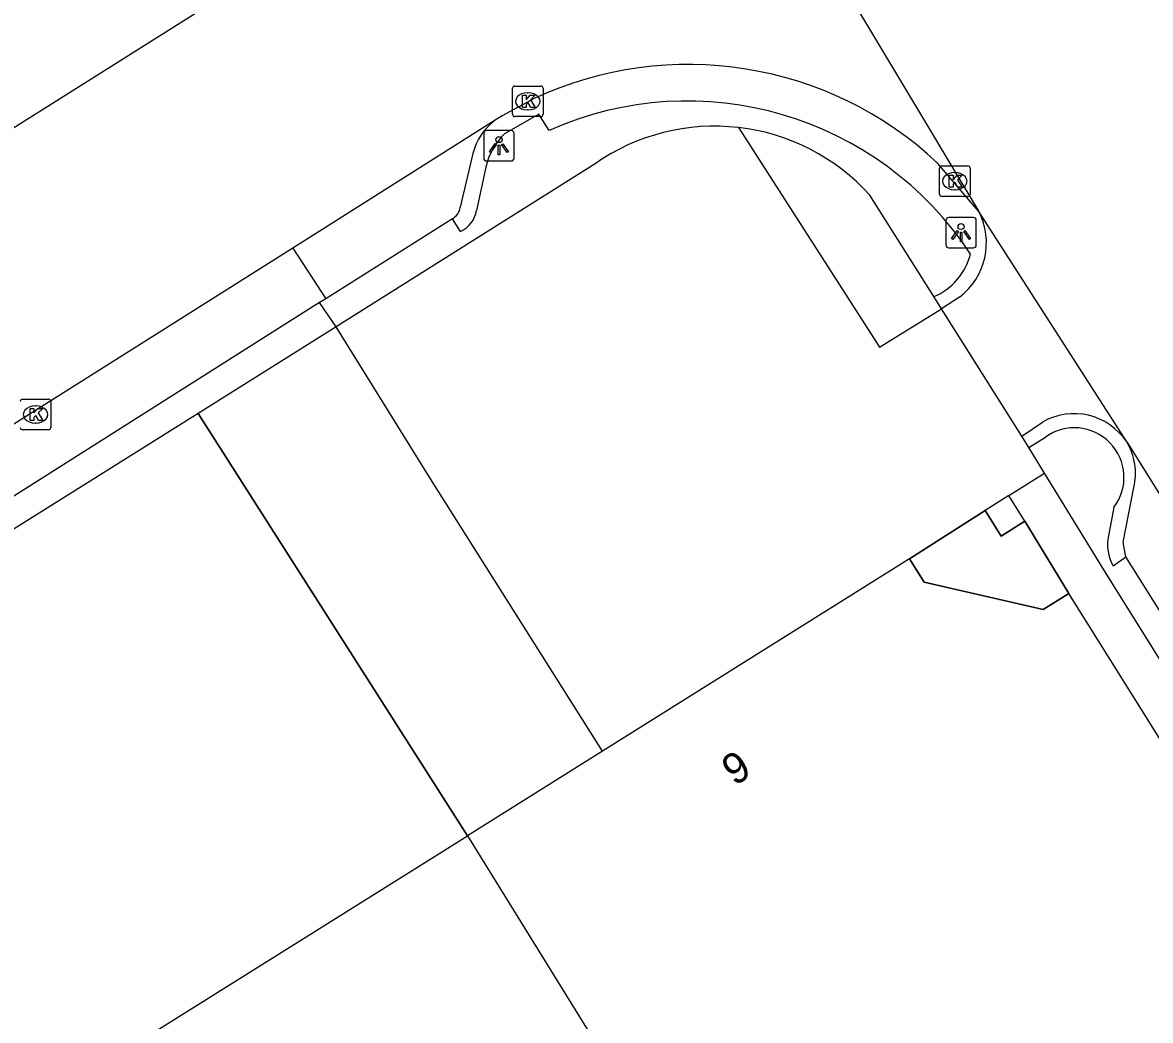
# Model space of a CAD drawing. Extents: x 158461 to 159795, y 387220 to 388672.
# Drawn here: x 158632.42 to 158669.4, y 387794.72 to 387827.43 of the extents above; entities that cross this region are included whole.
import ezdxf

# ---------------------------------------------------------------- set-up
doc = ezdxf.new("R2010")
doc.units = 0
for name, color, linetype in [('IMGEO_Hek', 7, 'Continuous'), ('IMGEO_Kolk', 7, 'Continuous'), ('IMGEO_Lichtpunt', 7, 'Continuous'), ('IMGEO_Pand', 7, 'Continuous'), ('IMGEO_Pand_nummerreeks', 7, 'Continuous'), ('IMGEO_Pand_overbouw', 7, 'Continuous'), ('IMGEO_Parkeervlak_open', 7, 'Continuous'), ('IMGEO_Rijbaan_lokaal_gesloten', 7, 'Continuous'), ('IMGEO_Rijbaan_lokaal_open', 7, 'Continuous'), ('IMGEO_Voetpad_open', 7, 'Continuous')]:
    doc.layers.add(name, color=color, linetype=linetype)

msp = doc.modelspace()

# ---------------------------------------------------------------- linework, layer by layer
at = {"layer": 'IMGEO_Hek'}
msp.add_lwpolyline([(158647.008, 387800.772), (158638.179, 387814.618)], dxfattribs=at)
at = {"layer": 'IMGEO_Kolk'}
for p, q in [((158648.49, 387824.421), (158648.49, 387825.273)), ((158648.565, 387825.347), (158649.417, 387825.347)), ((158648.978, 387825.127), (158649.003, 387825.127)), ((158649.491, 387825.273), (158649.491, 387824.421)), ((158649.417, 387824.347), (158648.565, 387824.347)), ((158649.001, 387824.567), (158648.976, 387824.567)), ((158662.489, 387821.803), (158662.489, 387822.655)), ((158662.564, 387822.729), (158663.416, 387822.729)), ((158662.977, 387822.509), (158663.002, 387822.509)), ((158663.49, 387822.655), (158663.49, 387821.803)), ((158663.416, 387821.729), (158662.564, 387821.729)), ((158663, 387821.949), (158662.975, 387821.949)), ((158632.424, 387815.082), (158633.276, 387815.082)), ((158632.837, 387814.862), (158632.862, 387814.862)), ((158633.35, 387815.008), (158633.35, 387814.156)), ((158633.276, 387814.082), (158632.424, 387814.082)), ((158632.86, 387814.302), (158632.835, 387814.302))]:
    msp.add_line(p, q, dxfattribs=at)
for points in [[(158648.49, 387824.421), (158648.49, 387825.273)], [(158648.565, 387825.347), (158649.417, 387825.347)], [(158648.811, 387825.047), (158648.934, 387825.047), (158648.934, 387824.896), (158649.064, 387825.047), (158649.228, 387825.047), (158649.082, 387824.896), (158649.235, 387824.647), (158649.083, 387824.647), (158648.998, 387824.811), (158648.934, 387824.744), (158648.934, 387824.647), (158648.811, 387824.647), (158648.811, 387825.047)], [(158649.491, 387825.273), (158649.491, 387824.421)], [(158649.417, 387824.347), (158648.565, 387824.347)], [(158662.489, 387821.803), (158662.489, 387822.655)], [(158662.564, 387822.729), (158663.416, 387822.729)], [(158663.49, 387822.655), (158663.49, 387821.803)], [(158662.81, 387822.429), (158662.933, 387822.429), (158662.933, 387822.278), (158663.063, 387822.429), (158663.227, 387822.429), (158663.081, 387822.278), (158663.234, 387822.029), (158663.082, 387822.029), (158662.997, 387822.193), (158662.933, 387822.126), (158662.933, 387822.029), (158662.81, 387822.029), (158662.81, 387822.429)], [(158663.416, 387821.729), (158662.564, 387821.729)], [(158632.424, 387815.082), (158633.276, 387815.082)], [(158632.67, 387814.782), (158632.793, 387814.782), (158632.793, 387814.631), (158632.923, 387814.782), (158633.087, 387814.782), (158632.941, 387814.631), (158633.094, 387814.382), (158632.942, 387814.382), (158632.857, 387814.546), (158632.793, 387814.479), (158632.793, 387814.382), (158632.67, 387814.382), (158632.67, 387814.782)], [(158633.35, 387815.008), (158633.35, 387814.156)], [(158633.276, 387814.082), (158632.424, 387814.082)]]:
    msp.add_lwpolyline(points, dxfattribs=at)
for centre, start, end in [((158648.567, 387825.271), 91.552, 178.448), ((158648.567, 387825.271), 91.552, 178.448), ((158649.415, 387825.271), 1.552, 88.448), ((158649.415, 387825.271), 1.552, 88.448), ((158648.567, 387824.423), 181.552, 268.448), ((158648.567, 387824.423), 181.552, 268.448), ((158649.415, 387824.423), 271.552, 358.448), ((158649.415, 387824.423), 271.552, 358.448), ((158662.566, 387822.653), 91.552, 178.448), ((158662.566, 387822.653), 91.552, 178.448), ((158663.414, 387822.653), 1.552, 88.448), ((158663.414, 387822.653), 1.552, 88.448), ((158662.566, 387821.805), 181.552, 268.448), ((158662.566, 387821.805), 181.552, 268.448), ((158663.414, 387821.805), 271.552, 358.448), ((158663.414, 387821.805), 271.552, 358.448), ((158632.426, 387815.006), 91.552, 178.448), ((158632.426, 387815.006), 91.552, 178.448), ((158633.274, 387815.006), 1.552, 88.448), ((158633.274, 387815.006), 1.552, 88.448), ((158632.426, 387814.158), 181.552, 268.448), ((158632.426, 387814.158), 181.552, 268.448), ((158633.274, 387814.158), 271.552, 358.448), ((158633.274, 387814.158), 271.552, 358.448)]:
    msp.add_arc(centre, 0.0765, start, end, dxfattribs=at)
for centre, major_axis, ratio, start_param, end_param in [((158648.977, 387824.847), (-0.387, 0.002), 0.722429, 4.712389, 7.853982), ((158649.002, 387824.847), (-0.39, 0.002), 0.717154, 1.570796, 4.712389), ((158662.976, 387822.229), (-0.387, 0.002), 0.722429, 4.712389, 7.853982), ((158663.001, 387822.229), (-0.39, 0.002), 0.717154, 1.570796, 4.712389), ((158632.836, 387814.582), (-0.387, 0.002), 0.722429, 4.712389, 7.853982), ((158632.861, 387814.582), (-0.39, 0.002), 0.717154, 1.570796, 4.712389)]:
    msp.add_ellipse(centre, major_axis=major_axis, ratio=ratio, start_param=start_param, end_param=end_param, dxfattribs=at)
at = {"layer": 'IMGEO_Lichtpunt'}
for p, q in [((158647.546, 387823.795), (158647.546, 387822.988)), ((158647.546, 387823.795), (158647.546, 387822.988)), ((158648.448, 387823.89), (158647.64, 387823.89)), ((158648.448, 387823.89), (158647.64, 387823.89)), ((158648.542, 387822.988), (158648.542, 387823.795)), ((158648.542, 387822.988), (158648.542, 387823.795)), ((158647.64, 387822.894), (158648.448, 387822.894)), ((158647.64, 387822.894), (158648.448, 387822.894)), ((158663.599, 387821.04), (158662.791, 387821.04)), ((158663.599, 387821.04), (158662.791, 387821.04)), ((158662.697, 387820.945), (158662.697, 387820.138)), ((158662.697, 387820.945), (158662.697, 387820.138)), ((158663.693, 387820.138), (158663.693, 387820.945)), ((158663.693, 387820.138), (158663.693, 387820.945)), ((158662.791, 387820.044), (158663.599, 387820.044)), ((158662.791, 387820.044), (158663.599, 387820.044))]:
    msp.add_line(p, q, dxfattribs=at)
for points in [[(158647.92, 387823.459), (158647.959, 387823.431), (158647.771, 387823.169), (158647.733, 387823.196), (158647.92, 387823.459)], [(158648.022, 387823.411), (158648.069, 387823.411), (158648.069, 387823.089), (158648.022, 387823.089), (158648.022, 387823.411)], [(158648.132, 387823.431), (158648.17, 387823.458), (158648.357, 387823.196), (158648.318, 387823.168), (158648.132, 387823.431)], [(158663.071, 387820.609), (158663.11, 387820.581), (158662.922, 387820.319), (158662.884, 387820.346), (158663.071, 387820.609)], [(158663.283, 387820.581), (158663.321, 387820.608), (158663.508, 387820.346), (158663.469, 387820.318), (158663.283, 387820.581)], [(158663.173, 387820.561), (158663.22, 387820.561), (158663.22, 387820.239), (158663.173, 387820.239), (158663.173, 387820.561)]]:
    msp.add_lwpolyline(points, dxfattribs=at)
for centre in [(158648.045, 387823.593), (158663.196, 387820.743)]:
    msp.add_circle(centre, 0.0994, dxfattribs=at)
for centre, start, end in [((158647.64, 387823.795), 90, 180), ((158647.64, 387823.795), 90, 180), ((158648.448, 387823.795), 0, 90), ((158648.448, 387823.795), 0, 90), ((158647.64, 387822.988), 180, 270), ((158647.64, 387822.988), 180, 270), ((158648.448, 387822.988), 270, 0), ((158648.448, 387822.988), 270, 360), ((158662.791, 387820.945), 90, 180), ((158662.791, 387820.945), 90, 180), ((158663.599, 387820.945), 0, 90), ((158663.599, 387820.945), 0, 90), ((158662.791, 387820.138), 180, 270), ((158662.791, 387820.138), 180, 270), ((158663.599, 387820.138), 270, 0), ((158663.599, 387820.138), 270, 360)]:
    msp.add_arc(centre, 0.0946, start, end, dxfattribs=at)
at = {"layer": 'IMGEO_Pand'}
for points in [[(158664.762, 387811.924), (158663.982, 387811.435)], [(158665.289, 387811.083), (158664.762, 387811.924)], [(158663.982, 387811.435), (158664.509, 387810.595), (158665.289, 387811.083)], [(158661.505, 387809.854), (158651.443, 387803.55)], [(158666.728, 387808.713), (158665.888, 387808.187), (158661.989, 387809.082), (158661.505, 387809.854)], [(158684.676, 387780.065), (158666.728, 387808.713)], [(158651.443, 387803.55), (158647.008, 387800.772)], [(158632.509, 387791.689), (158647.008, 387800.772)], [(158647.008, 387800.772), (158666.776, 387768.852)]]:
    msp.add_lwpolyline(points, dxfattribs=at)
at = {"layer": 'IMGEO_Pand_overbouw'}
msp.add_lwpolyline([(158663.982, 387811.435), (158661.505, 387809.854), (158661.989, 387809.082), (158665.888, 387808.187), (158666.728, 387808.713), (158665.289, 387811.083), (158664.509, 387810.595)], close=True, dxfattribs=at)
at = {"layer": 'IMGEO_Parkeervlak_open'}
for points in [[(158655.894, 387823.988), (158660.518, 387816.789), (158662.554, 387818.05)], [(158664.762, 387811.924), (158665.935, 387812.659)]]:
    msp.add_lwpolyline(points, dxfattribs=at)
at = {"layer": 'IMGEO_Rijbaan_lokaal_gesloten'}
for points in [[(158648.193, 387847.22), (158648.302, 387847.052), (158663.777, 387821.236)], [(158643.611, 387831.215), (158616.891, 387814.387)], [(158649.201, 387824.938), (158648.154, 387824.373), (158647.919, 387824.224)], [(158647.919, 387824.224), (158641.284, 387820.03)], [(158663.777, 387821.236), (158662.427, 387822.825)], [(158668.626, 387813.681), (158663.777, 387821.236)], [(158641.284, 387820.03), (158623.48, 387808.816), (158622.522, 387808.14), (158621.407, 387807.18)], [(158668.626, 387813.681), (158682.44, 387791.58)]]:
    msp.add_lwpolyline(points, dxfattribs=at)
msp.add_arc((158654.249, 387814.087), 11.968, 46.8968, 114.9494, dxfattribs=at)
at = {"layer": 'IMGEO_Rijbaan_lokaal_open'}
for points in [[(158642.709, 387817.456), (158638.179, 387814.618)], [(158651.443, 387803.55), (158645.8, 387812.47), (158642.709, 387817.456)], [(158638.179, 387814.618), (158647.008, 387800.772)]]:
    msp.add_lwpolyline(points, dxfattribs=at)
at = {"layer": 'IMGEO_Voetpad_open'}
for points in [[(158649.691, 387823.894), (158649.354, 387824.421), (158648.223, 387823.784)], [(158647.19, 387823.138), (158646.775, 387821.375)], [(158651.194, 387822.802), (158642.709, 387817.456)], [(158647.613, 387822.692), (158647.312, 387821.271)], [(158662.302, 387818.444), (158660.204, 387821.771)], [(158646.516, 387820.997), (158642.372, 387818.373)], [(158646.786, 387820.582), (158646.516, 387820.997)], [(158641.284, 387820.03), (158642.372, 387818.373)], [(158662.554, 387818.05), (158662.302, 387818.444)], [(158663.143, 387818.432), (158662.554, 387818.05)], [(158642.164, 387818.251), (158625.053, 387807.424)], [(158642.372, 387818.373), (158642.164, 387818.251)], [(158642.709, 387817.456), (158642.164, 387818.251)], [(158665.191, 387813.87), (158662.554, 387818.05)], [(158638.179, 387814.618), (158625.548, 387806.705)], [(158665.191, 387813.87), (158665.861, 387814.333)], [(158665.421, 387813.498), (158665.191, 387813.87)], [(158665.421, 387813.498), (158665.962, 387813.837)], [(158665.935, 387812.659), (158665.421, 387813.498)], [(158697.853, 387761.514), (158667.897, 387809.455), (158665.935, 387812.659)], [(158668.593, 387809.918), (158668.512, 387810.397), (158668.857, 387812.187)], [(158661.505, 387809.854), (158663.982, 387811.435)], [(158668.207, 387811.543), (158668.01, 387810.49)], [(158665.289, 387811.083), (158666.728, 387808.713)], [(158668.184, 387809.62), (158668.593, 387809.918)], [(158680.765, 387790.537), (158679.183, 387793.077), (158668.593, 387809.918)]]:
    msp.add_lwpolyline(points, dxfattribs=at)
for centre, radius, start, end in [((158654.213, 387813.745), 11.111, 33.263, 114.0163), ((158649.071, 387822.663), 1.94, 126.424, 165.8314), ((158655.114, 387817.172), 6.86, 83.474, 124.8508), ((158655.114, 387817.173), 6.86, 42.0917, 83.467), ((158649.767, 387822.205), 2.208, 134.3575, 167.2664), ((158646.275, 387821.44), 0.504, 298.5569, 352.6063), ((158646.366, 387821.448), 0.963, 295.8788, 349.4032), ((158661.784, 387820.213), 2.241, 307.3536, 27.1651), ((158661.492, 387820.357), 2.077, 292.9393, 345.5612), ((158666.897, 387812.537), 2.073, 33.4822, 119.9813), ((158666.914, 387812.523), 1.623, 322.8535, 125.9095), ((158666.95, 387812.657), 1.964, 346.1573, 31.4214), ((158669.377, 387810.311), 1.378, 172.5332, 210.0867)]:
    msp.add_arc(centre, radius, start, end, dxfattribs=at)

# ---------------------------------------------------------------- texts
at = {"layer": 'IMGEO_Pand_nummerreeks'}
msp.add_text('9', height=1, rotation=32.0657, dxfattribs=at).set_placement((158655.764, 387802.387))

doc.saveas('drawing.dxf')
